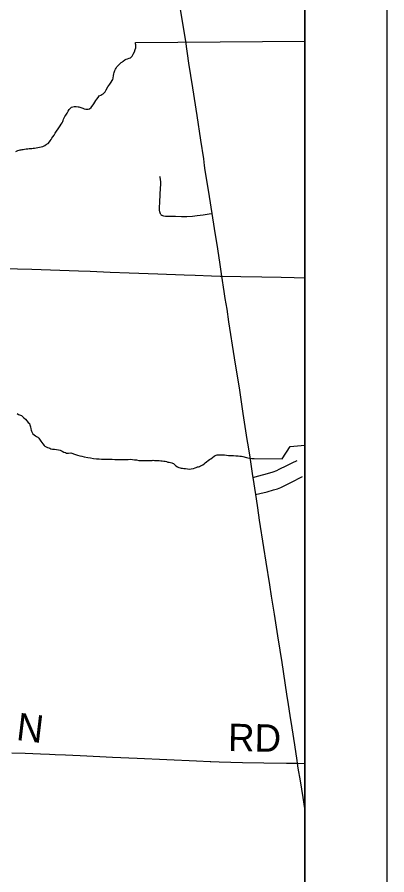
# Model space of a CAD drawing. Extents: x -483 to 680, y 0 to 440.
# Drawn here: x 355.8 to 394.1, y 160 to 248.8 of the extents above; entities that cross this region are included whole.
import ezdxf

# ---------------------------------------------------------------- set-up
doc = ezdxf.new("R2010")
doc.units = 0
for name, color, linetype in [('GM_X_County_Road', 7, 'Continuous'), ('GM_X_Minor_River', 7, 'Continuous'), ('GM_X_State_Route', 7, 'Continuous'), ('GM_X_Township_Road', 7, 'Continuous'), ('GM_X_Township_Road_Text', 7, 'Continuous'), ('SH_Cut_Line', 7, 'Continuous'), ('SH_Text', 7, 'Continuous')]:
    doc.layers.add(name, color=color, linetype=linetype)

msp = doc.modelspace()

# ---------------------------------------------------------------- linework, layer by layer
at = {"layer": 'GM_X_County_Road'}
for points in [[(354.144, 222.828), (355.847, 222.767), (357.307, 222.719), (362.153, 222.539), (363.364, 222.494), (365.445, 222.422), (367.402, 222.34), (370.384, 222.246), (373.117, 222.135), (374.235, 222.09), (375.947, 222.028), (376.827, 221.996), (376.98, 221.99)], [(376.98, 221.99), (378.985, 221.961), (381.161, 221.926), (383.15, 221.875), (384.517, 221.84), (385.608, 221.819)]]:
    msp.add_lwpolyline(points, dxfattribs=at)
at = {"layer": 'GM_X_Minor_River'}
msp.add_line((368.078, 246.181), (385.608, 246.313), dxfattribs=at)
for points in [[(359.314, 236.134), (359.393, 236.266), (359.511, 236.434), (359.629, 236.603), (359.747, 236.81), (359.885, 237.016), (360.042, 237.241), (360.258, 237.541), (360.376, 237.728), (360.455, 237.86), (360.515, 237.992), (360.556, 238.105), (360.616, 238.237), (360.676, 238.369), (360.736, 238.52), (360.834, 238.651), (360.912, 238.763), (360.972, 238.857), (361.012, 238.952), (361.071, 239.065), (361.189, 239.233), (361.267, 239.327), (361.442, 239.475), (361.576, 239.51), (361.691, 239.546), (361.805, 239.562), (361.92, 239.56), (362.109, 239.536), (362.204, 239.515), (362.299, 239.475), (362.393, 239.454), (362.507, 239.413), (362.62, 239.392), (362.752, 239.332), (362.904, 239.29), (363.056, 239.287), (363.17, 239.284), (363.285, 239.301), (363.478, 239.449), (363.753, 239.824), (363.833, 239.993), (363.951, 240.181), (364.068, 240.331), (364.186, 240.48), (364.304, 240.649), (364.458, 240.741), (364.574, 240.814), (364.708, 240.868), (364.903, 241.073), (365.022, 241.28), (365.2, 241.6), (365.396, 241.881), (365.553, 242.087), (365.651, 242.237), (365.711, 242.35), (365.752, 242.501), (365.777, 242.767), (365.819, 242.938), (365.86, 243.089), (365.922, 243.297), (365.981, 243.41), (366.06, 243.522), (366.139, 243.654), (366.275, 243.803), (366.431, 243.971), (366.586, 244.101), (366.702, 244.174), (366.799, 244.267), (366.973, 244.378), (367.108, 244.451), (367.242, 244.505), (367.396, 244.559), (367.53, 244.594), (367.646, 244.686), (367.724, 244.78), (367.824, 244.987), (367.943, 245.213), (368.043, 245.458), (368.104, 245.647), (368.107, 245.78), (368.092, 245.952), (368.075, 246.047), (368.078, 246.181), (368.077, 246.161)], [(355.67, 234.901), (355.862, 234.992), (355.996, 235.027), (356.111, 235.063), (356.207, 235.061), (356.322, 235.096), (356.436, 235.113), (356.57, 235.148), (356.723, 235.164), (356.895, 235.179), (357.028, 235.195), (357.181, 235.211), (357.315, 235.227), (357.448, 235.243), (357.6, 235.239), (357.772, 235.274), (358.442, 235.43), (358.654, 235.52), (358.828, 235.65), (359.02, 235.741), (359.156, 235.89), (359.235, 236.003), (359.314, 236.134)], [(355.795, 207.773), (355.946, 207.675), (356.134, 207.595), (356.248, 207.573), (356.36, 207.456), (356.49, 207.32), (356.659, 207.183), (356.807, 207.009), (356.956, 206.853), (357.068, 206.736), (357.122, 206.602), (357.175, 206.391), (357.227, 206.181), (357.263, 206.047), (357.299, 205.951), (357.353, 205.816), (357.426, 205.681), (357.557, 205.564), (357.707, 205.466), (357.801, 205.388), (357.932, 205.309), (358.045, 205.23), (358.174, 205.018), (358.266, 204.901), (358.359, 204.766), (358.47, 204.63), (358.581, 204.476), (358.674, 204.378), (358.788, 204.338), (358.938, 204.258), (359.07, 204.217), (359.184, 204.177), (359.278, 204.118), (359.468, 204.094), (359.658, 204.071), (359.867, 204.047), (360.076, 204.024), (360.265, 203.981), (360.453, 203.882), (360.623, 203.783), (360.793, 203.722), (360.925, 203.662), (361.02, 203.66), (361.134, 203.658), (361.344, 203.691), (361.836, 203.528), (362.062, 203.447), (362.29, 203.385), (362.498, 203.342), (362.744, 203.279), (363.124, 203.233), (363.389, 203.17), (363.712, 203.125), (364.035, 203.098), (364.282, 203.074), (364.548, 203.049), (364.777, 203.044), (364.967, 203.04), (365.176, 203.035), (365.405, 203.049), (365.652, 203.043), (365.918, 203.018), (366.28, 203.01), (366.546, 203.004), (366.832, 202.998), (367.099, 203.011), (367.308, 203.026), (367.518, 203.04), (367.746, 203.016), (367.955, 202.992), (368.164, 202.969), (368.411, 202.925), (368.677, 202.9), (368.943, 202.894), (369.134, 202.909), (369.362, 202.904), (369.591, 202.899), (369.781, 202.914), (369.896, 202.93), (370.029, 202.908), (370.181, 202.905), (370.333, 202.901), (370.504, 202.898), (370.695, 202.893), (370.827, 202.871), (370.998, 202.849), (371.131, 202.827), (371.264, 202.805), (371.415, 202.744), (371.567, 202.722), (371.7, 202.7), (371.813, 202.678), (371.908, 202.638), (372.002, 202.598)], [(380.372, 203.116), (383.246, 203.09), (384.092, 204.347), (385.608, 204.51)], [(372.002, 202.598), (372.245, 202.364), (372.414, 202.246), (372.565, 202.186), (372.697, 202.145), (372.791, 202.104), (372.925, 202.102), (373.058, 202.099), (373.229, 202.076), (373.437, 202.033), (373.685, 202.028), (373.838, 202.062), (374.067, 202.095), (374.24, 202.167), (374.355, 202.203), (374.47, 202.238), (374.584, 202.255), (374.68, 202.291), (374.796, 202.345), (374.911, 202.4), (375.046, 202.473), (375.181, 202.565), (375.297, 202.658), (375.434, 202.788), (375.608, 202.917), (375.724, 203.01), (375.878, 203.083), (376.033, 203.213), (376.207, 203.342), (376.304, 203.435), (376.515, 203.488), (376.705, 203.502), (376.877, 203.499), (377.01, 203.495), (377.124, 203.493), (377.295, 203.489), (377.485, 203.466), (377.694, 203.442), (377.884, 203.438), (378.055, 203.415), (378.227, 203.411), (378.474, 203.406), (378.683, 203.401), (378.873, 203.359), (379.044, 203.355), (379.177, 203.314), (379.575, 203.229), (379.707, 203.188), (379.859, 203.166), (379.973, 203.144), (380.105, 203.103), (380.219, 203.101), (380.296, 203.118), (380.372, 203.116)]]:
    msp.add_lwpolyline(points, dxfattribs=at)
at = {"layer": 'GM_X_State_Route'}
for points in [[(372.701, 249.636), (373.226, 246.289), (373.567, 244.046), (373.97, 241.498), (374.402, 238.639), (374.787, 236.089), (375.092, 234.153), (375.188, 233.445), (375.262, 232.923), (375.454, 231.726), (375.691, 230.253), (375.976, 228.481), (376.047, 228.043), (376.316, 226.261), (376.474, 225.279), (376.757, 223.435), (376.98, 221.99)], [(376.98, 221.99), (377.226, 220.394), (377.333, 219.688), (377.515, 218.583), (377.713, 217.261), (378.301, 213.547), (378.821, 210.199), (379.196, 207.771), (379.39, 206.418), (379.609, 205.069), (379.72, 204.331), (379.895, 203.257), (380.191, 201.321), (380.216, 201.156), (380.489, 199.389), (380.555, 198.956), (380.705, 198.004), (380.89, 196.743), (381.341, 193.888), (381.571, 192.382), (381.937, 190.048), (382.125, 188.851), (382.422, 187.01), (382.772, 184.768), (383.002, 183.263), (383.212, 182.005), (383.707, 178.717), (383.876, 177.642), (384.05, 176.505), (384.265, 175.218), (384.545, 173.468), (384.784, 171.869), (384.828, 171.562), (384.899, 171.069), (385.113, 169.751), (385.384, 168.031), (385.608, 166.626)]]:
    msp.add_lwpolyline(points, dxfattribs=at)
at = {"layer": 'GM_X_Township_Road'}
msp.add_line((384.828, 171.562), (385.608, 171.538), dxfattribs=at)
for points in [[(370.696, 228.389), (370.647, 228.461), (370.606, 228.545), (370.573, 228.655), (370.557, 228.818), (370.557, 229.097), (370.587, 229.654), (370.633, 230.435), (370.667, 231.087), (370.683, 231.488), (370.681, 231.768), (370.664, 231.999), (370.612, 232.229), (370.569, 232.323)], [(370.696, 228.389), (370.783, 228.322), (370.867, 228.285), (370.976, 228.248), (371.157, 228.215), (371.392, 228.194), (372.19, 228.188), (372.842, 228.178), (373.369, 228.182), (373.96, 228.206), (374.45, 228.263), (375.065, 228.344), (375.678, 228.436), (375.976, 228.481)], [(380.216, 201.156), (380.831, 201.31), (381.744, 201.549), (382.33, 201.746), (382.705, 201.891), (382.957, 202.004), (383.218, 202.142), (383.464, 202.256), (383.872, 202.451), (384.507, 202.761), (384.62, 202.815), (384.815, 202.903)], [(380.489, 199.389), (380.935, 199.507), (381.692, 199.681), (382.351, 199.86), (382.767, 199.985), (383.107, 200.101), (383.542, 200.307), (384.143, 200.631), (385.353, 201.268)], [(355.262, 172.66), (356.635, 172.612), (358.206, 172.557), (359.137, 172.508), (359.727, 172.479), (360.813, 172.429), (362.335, 172.356), (364.354, 172.268), (365.688, 172.205), (368.235, 172.091), (374.383, 171.813), (375.806, 171.753)], [(375.806, 171.753), (375.855, 171.751), (376.744, 171.714), (379.137, 171.656), (381.375, 171.608), (383.707, 171.572), (384.484, 171.565), (384.828, 171.562)]]:
    msp.add_lwpolyline(points, dxfattribs=at)
at = {"layer": 'SH_Cut_Line'}
msp.add_lwpolyline([(385.608, 55.95), (385.608, 395.95)], dxfattribs=at)
at = {"layer": 'SH_Text'}
for points in [[(37.108, 404.45), (394.108, 404.45), (394.108, 47.45), (37.108, 47.45)], [(45.608, 395.95), (385.608, 395.95), (385.608, 55.95), (45.608, 55.95)]]:
    msp.add_lwpolyline(points, close=True, dxfattribs=at)

# ---------------------------------------------------------------- texts
at = {"layer": 'GM_X_Township_Road_Text'}
for s, height, rotation, p in [('N', 2.841, 353.12111, (355.629, 173.987)), ('RD', 2.8409, 359.02233, (377.636, 172.83))]:
    msp.add_text(s, height=height, rotation=rotation, dxfattribs=at).set_placement(p)

doc.saveas('drawing.dxf')
